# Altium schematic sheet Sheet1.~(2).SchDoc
size A3
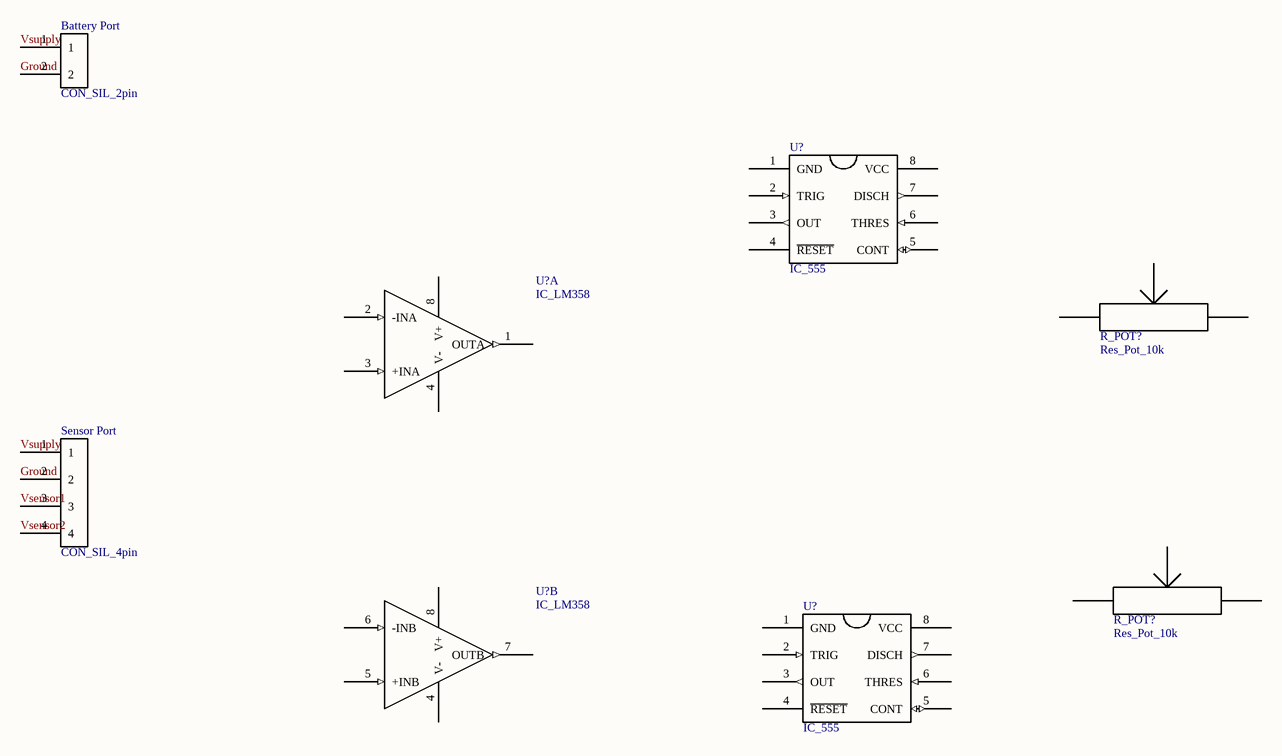
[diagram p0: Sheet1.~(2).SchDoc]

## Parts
(Parts that share a designator on the sheet are numbered #1, #2 ... from top to bottom, then left to right.)
Battery_Port  CON_SIL_2pin  [ece-HDR1X2]
R_POT?#1  Res_Pot_10k  [POT]
R_POT?#2  Res_Pot_10k  [POT]
Sensor_Port  CON_SIL_4pin  [ece-HDR1X4]
U?#1  IC_555  [DIP_8]
U?#2  IC_LM358  [DIP_8]  (part A of 2)
U?#3  IC_LM358  [DIP_8]  (part B of 2)
U?#4  IC_555  [DIP_8]

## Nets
Ground: Battery_Port.2 Sensor_Port.2
Vsensor1: Sensor_Port.3
Vsensor2: Sensor_Port.4
Vsupply: Battery_Port.1 Sensor_Port.1

Not connected (* = marked no-connect by the designer): R_POT?#1 1 2 3; R_POT?#2 1 2 3; U?#1 1(GND) 2(TRIG) 3(OUT) 4(~{RESET}) 5(CONT) 6(THRES) 7(DISCH) 8(VCC); U?#2 1(OUTA) 2(-INA) 3(+INA) 4(V-) 8(V+); U?#3 4(V-) 5(+INB) 6(-INB) 7(OUTB) 8(V+); U?#4 1(GND) 2(TRIG) 3(OUT) 4(~{RESET}) 5(CONT) 6(THRES) 7(DISCH) 8(VCC)

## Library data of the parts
Battery_Port = CON_SIL_2pin: 2 pin in line connector
Sensor_Port = CON_SIL_4pin: 4 pin in line connector
U?#1 U?#4 = IC_555: NEC555
U?#2 U?#3 = IC_LM358: LM358 - Dual Opamp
